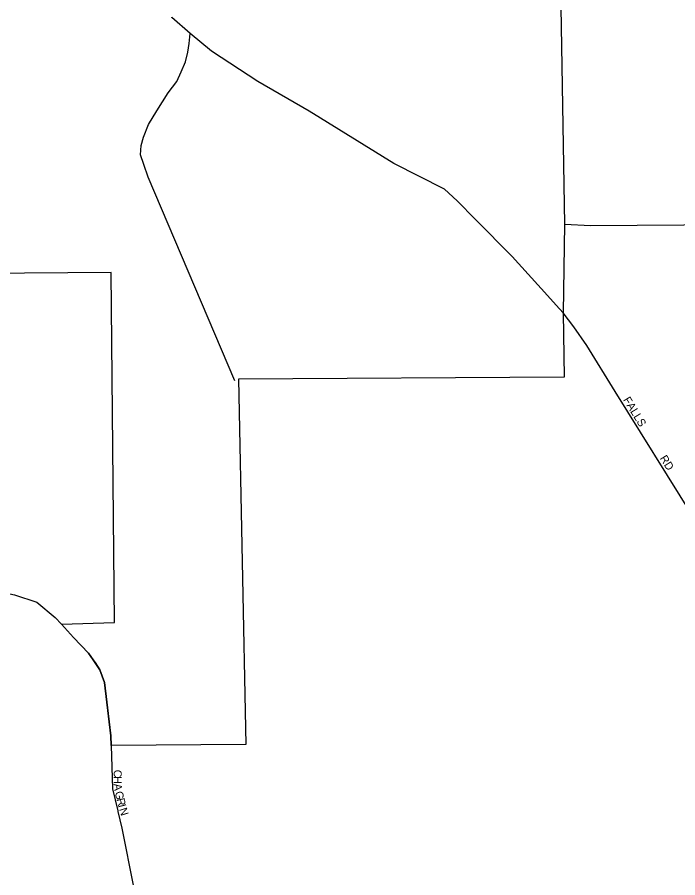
# Model space of a CAD drawing. Extents: x -561 to 1170, y 0 to 846.
# Drawn here: x 457.18 to 468.32, y 226.72 to 241.23 of the extents above; entities that cross this region are included whole.
import ezdxf

# ---------------------------------------------------------------- set-up
doc = ezdxf.new("R2010")
doc.units = 0
for name, color, linetype in [('GM_X_City_Street', 7, 'Continuous'), ('GM_X_City_Street_Text', 7, 'Continuous'), ('GM_X_County', 7, 'Continuous'), ('GM_X_County_Road', 7, 'Continuous'), ('GM_X_Township', 7, 'Continuous')]:
    doc.layers.add(name, color=color, linetype=linetype)

msp = doc.modelspace()

# ---------------------------------------------------------------- linework, layer by layer
at = {"layer": 'GM_X_City_Street'}
for points in [[(468.57, 232.819), (467.257, 234.92), (466.779, 235.699), (466.564, 236.011), (466.383, 236.247), (466.267, 236.376)], [(454.756, 232.034), (455.378, 231.806), (455.564, 231.74), (456.101, 231.566), (456.436, 231.565), (456.792, 231.564), (457.133, 231.493), (457.507, 231.369), (457.82, 231.108), (457.922, 230.996), (458.125, 230.773), (458.377, 230.511), (458.46, 230.398), (458.489, 230.353)], [(458.739, 229.255), (458.756, 229.114), (458.761, 228.953), (458.782, 228.223), (458.872, 227.85), (458.874, 227.842)], [(458.874, 227.842), (458.942, 227.559), (459.139, 226.571), (459.266, 225.939), (459.406, 225.627), (460.153, 225.106), (460.32, 224.973), (460.329, 224.966)]]:
    msp.add_lwpolyline(points, dxfattribs=at)
at = {"layer": 'GM_X_County'}
msp.add_lwpolyline([(466.148, 281.711), (466.276, 259.428), (466.313, 253.936), (466.279, 251.796), (466.28, 247.567), (466.28, 245.072), (466.408, 237.742), (466.848, 237.719), (471.546, 237.752), (478.016, 237.883), (478.739, 226.426), (478.848, 224.815), (479.164, 220.147), (479.331, 217.621), (477.752, 217.584), (469.804, 217.395), (466.368, 217.313), (466.37, 216.798), (466.375, 215.749), (466.382, 214.541), (466.407, 209.575)], dxfattribs=at)
at = {"layer": 'GM_X_County_Road'}
for points in [[(466.267, 236.376), (466.117, 236.543), (465.521, 237.199), (464.902, 237.823), (464.596, 238.135), (464.381, 238.334), (463.529, 238.764), (462.1, 239.651), (461.232, 240.148), (460.455, 240.662), (460.096, 240.957), (459.786, 241.23), (459.783, 241.233)], [(460.849, 235.101), (459.385, 238.535), (459.31, 238.751), (459.257, 238.91), (459.268, 239.068), (459.304, 239.211), (459.389, 239.423), (459.533, 239.652), (459.72, 239.957), (459.87, 240.148), (459.944, 240.311), (460.013, 240.479), (460.055, 240.642), (460.075, 240.789), (460.096, 240.957)], [(458.489, 230.353), (458.569, 230.228), (458.647, 230.015), (458.739, 229.255)]]:
    msp.add_lwpolyline(points, dxfattribs=at)
at = {"layer": 'GM_X_Township'}
msp.add_lwpolyline([(466.28, 245.072), (466.408, 237.742), (466.383, 236.247), (466.397, 235.162), (460.91, 235.131), (461.032, 228.971), (458.761, 228.953), (458.756, 229.114), (458.647, 230.015), (458.569, 230.229), (458.46, 230.398), (458.377, 230.511), (458.125, 230.773), (457.922, 230.996), (458.817, 231.025), (458.763, 236.929), (455.101, 236.899)], dxfattribs=at)

# ---------------------------------------------------------------- texts
at = {"layer": 'GM_X_City_Street_Text'}
for s, rotation, p in [('FALLS', 301.4266, (467.389, 234.782)), ('RD', 301.9968, (468.007, 233.796)), ('C', 270.17, (458.804, 228.543)), ('H', 270.1729, (458.804, 228.436)), ('A', 275.1869, (458.805, 228.304)), ('G', 284.5673, (458.82, 228.162)), ('R', 284.531, (458.85, 228.047)), ('I', 285.0477, (458.877, 227.943)), ('N', 287.4372, (458.894, 227.879))]:
    msp.add_text(s, height=0.135, rotation=rotation, dxfattribs=at).set_placement(p)

doc.saveas('drawing.dxf')
